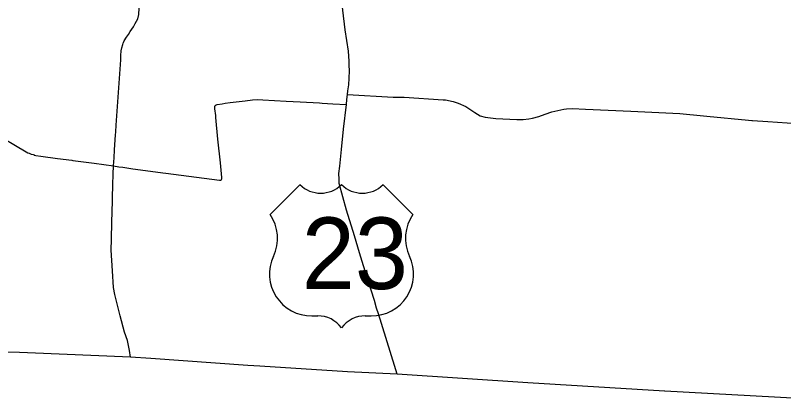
# Model space of a CAD drawing. Extents: x 0 to 34, y 0 to 22.
# Drawn here: x 5.072 to 6.458, y 14.434 to 15.124 of the extents above; entities that cross this region are included whole.
import ezdxf

# ---------------------------------------------------------------- set-up
doc = ezdxf.new("R2010")
doc.units = 0
for name, color, linetype in [('GM_X_County', 7, 'Continuous'), ('GM_X_State_Route', 7, 'Continuous'), ('GM_X_US_Route', 7, 'Continuous'), ('GM_X_US_Shield', 7, 'Continuous')]:
    doc.layers.add(name, color=color, linetype=linetype)

msp = doc.modelspace()

# ---------------------------------------------------------------- linework, layer by layer
at = {"layer": 'GM_X_County'}
msp.add_lwpolyline([(6.4853, 14.4341), (6.2434, 14.4473), (6.2427, 14.4474), (5.9966, 14.4624), (5.7606, 14.4783), (5.6711, 14.4822), (5.513, 14.4923), (5.4918, 14.4937), (5.3167, 14.5061), (5.2797, 14.5085), (5.0939, 14.5163), (5.08, 14.5169), (5.0551, 14.5178), (4.8851, 14.5227), (4.6999, 14.5295), (4.5093, 14.542), (4.3546, 14.5516), (4.3469, 14.5519), (4.1065, 14.5646)], dxfattribs=at)
at = {"layer": 'GM_X_State_Route'}
for points in [[(5.2669, 15.0743), (5.2673, 15.0755), (5.2687, 15.0786), (5.2726, 15.0851), (5.2761, 15.0899), (5.2796, 15.0952), (5.2855, 15.1033), (5.2886, 15.1093), (5.2929, 15.1182), (5.2948, 15.1255), (5.2956, 15.137), (5.2954, 15.1512), (5.2949, 15.1595)], [(5.2543, 14.9262), (5.2543, 14.9266), (5.2624, 15.0439), (5.2627, 15.0519), (5.2633, 15.0603), (5.2641, 15.0659), (5.2659, 15.0716), (5.2669, 15.0743)], [(5.6711, 14.982), (5.7537, 14.9772)], [(5.4336, 14.9438), (5.4322, 14.9561), (5.432, 14.96), (5.4328, 14.962), (5.4345, 14.9634), (5.4365, 14.964), (5.4455, 14.9652), (5.4509, 14.9659), (5.4599, 14.9672), (5.487, 14.9705), (5.4999, 14.9722), (5.5088, 14.9728), (5.5188, 14.9722)], [(5.5188, 14.9722), (5.5607, 14.9697), (5.5856, 14.9687), (5.621, 14.9666), (5.6256, 14.9664), (5.6451, 14.9652), (5.6692, 14.9635)], [(5.7537, 14.9772), (5.7562, 14.9771)], [(5.7562, 14.9771), (5.7668, 14.9772), (5.7732, 14.9768), (5.7733, 14.9768)], [(5.7733, 14.9768), (5.8438, 14.9721)], [(5.8438, 14.9721), (5.8438, 14.9721), (5.8477, 14.9719), (5.8616, 14.9694), (5.8708, 14.9664), (5.8845, 14.9599), (5.9011, 14.949), (5.9108, 14.9435), (5.9196, 14.9408), (5.9388, 14.9387), (5.9769, 14.9364), (5.988, 14.9366), (5.9985, 14.9381), (6.005, 14.9393), (6.0165, 14.9423), (6.0275, 14.9462), (6.04, 14.9506), (6.0453, 14.9519), (6.0503, 14.953), (6.0557, 14.954), (6.0612, 14.955), (6.0664, 14.9557), (6.077, 14.9563), (6.1006, 14.9553), (6.1825, 14.9515)], [(6.1825, 14.9515), (6.2707, 14.9474), (6.3135, 14.9431), (6.3191, 14.9426)], [(4.9733, 14.9467), (5.0253, 14.9173), (5.0305, 14.9147), (5.0915, 14.8785), (5.0945, 14.8768), (5.0974, 14.876), (5.1007, 14.8745), (5.1041, 14.8734), (5.1064, 14.8728), (5.1064, 14.8727)], [(5.3436, 14.8402), (5.4405, 14.8274), (5.4424, 14.8277), (5.4439, 14.8287), (5.4444, 14.8296), (5.4445, 14.8303), (5.4446, 14.832), (5.442, 14.8585), (5.4376, 14.9014), (5.434, 14.9404), (5.4336, 14.9438)], [(6.3191, 14.9426), (6.3945, 14.9353), (6.4007, 14.9349), (6.4018, 14.9349)], [(5.2535, 14.914), (5.2535, 14.9143), (5.2543, 14.9262)], [(6.4018, 14.9349), (6.4291, 14.9332), (6.4815, 14.9296), (6.4817, 14.9296)], [(5.2513, 14.8823), (5.2531, 14.9091)], [(5.2531, 14.9091), (5.2535, 14.914)], [(5.2503, 14.8677), (5.2513, 14.8823)], [(5.1064, 14.8727), (5.1091, 14.872), (5.1185, 14.8704), (5.1483, 14.8666), (5.1742, 14.8633)], [(5.2493, 14.8531), (5.2503, 14.8677)], [(5.1742, 14.8633), (5.1743, 14.8633), (5.1757, 14.8631), (5.2142, 14.8579), (5.2493, 14.8531)], [(5.2481, 14.819), (5.2486, 14.8382), (5.2493, 14.8531)], [(5.2493, 14.8531), (5.2589, 14.8517)], [(5.2589, 14.8517), (5.2662, 14.8507)], [(5.2662, 14.8507), (5.2843, 14.8481), (5.3339, 14.8415)], [(5.3339, 14.8415), (5.3382, 14.8409), (5.3436, 14.8402)], [(5.2473, 14.7898), (5.2474, 14.7956), (5.2481, 14.819)], [(5.2797, 14.5085), (5.278, 14.5204), (5.2745, 14.5386), (5.2693, 14.5537), (5.2615, 14.5831), (5.2515, 14.6213), (5.249, 14.6339), (5.2473, 14.6644), (5.2451, 14.7014), (5.2455, 14.7214), (5.2461, 14.7516), (5.2473, 14.7895), (5.2473, 14.7898)]]:
    msp.add_lwpolyline(points, dxfattribs=at)
at = {"layer": 'GM_X_US_Route'}
for points in [[(5.6735, 14.9989), (5.6736, 14.9995), (5.6744, 15.0107), (5.6748, 15.025), (5.6745, 15.0342), (5.6741, 15.0416), (5.673, 15.0597), (5.6673, 15.0983), (5.6628, 15.1338), (5.6567, 15.1857), (5.6515, 15.2308), (5.6393, 15.326), (5.6269, 15.4235), (5.6226, 15.4628), (5.6205, 15.4811), (5.6107, 15.5672), (5.6099, 15.575)], [(5.6711, 14.982), (5.672, 14.9883), (5.6735, 14.9989)], [(5.6692, 14.9635), (5.67, 14.973), (5.6711, 14.982)], [(5.6578, 14.8585), (5.6605, 14.8828), (5.6643, 14.9191), (5.6692, 14.9635)], [(5.6562, 14.8292), (5.6558, 14.8397), (5.6572, 14.8528), (5.6578, 14.8584), (5.6578, 14.8585)], [(5.6836, 14.7274), (5.6694, 14.7733), (5.6565, 14.8217), (5.6562, 14.8292)], [(5.7238, 14.597), (5.7197, 14.6106), (5.708, 14.6477), (5.693, 14.6966), (5.6836, 14.7274)], [(5.7606, 14.4783), (5.7559, 14.4934), (5.727, 14.5865), (5.7238, 14.597)]]:
    msp.add_lwpolyline(points, dxfattribs=at)
at = {"layer": 'GM_X_US_Shield'}
for p, q in [((5.5853, 14.8193), (5.5316, 14.7657)), ((5.7893, 14.7657), (5.7356, 14.8193)), ((5.6067, 14.5831), (5.6175, 14.5831)), ((5.7034, 14.5831), (5.7141, 14.5831))]:
    msp.add_line(p, q, dxfattribs=at)
for centre, radius, start, end in [((5.6229, 14.8577), 0.0537, 225.573, 314.427), ((5.698, 14.8577), 0.0537, 225.573, 314.427), ((5.47, 14.7225), 0.0752, 334.5471, 35.0009), ((5.8509, 14.7225), 0.0752, 144.9991, 205.4529), ((5.6059, 14.6583), 0.0752, 154.8319, 270.6383), ((5.715, 14.6583), 0.0752, 269.3617, 25.1681), ((5.6175, 14.5294), 0.0537, 36.8699, 90), ((5.7034, 14.5294), 0.0537, 90, 143.1301)]:
    msp.add_arc(centre, radius, start, end, dxfattribs=at)

# ---------------------------------------------------------------- texts
msp.add_text('23', height=0.12885, dxfattribs=at).set_placement((5.5887, 14.6314))

doc.saveas('drawing.dxf')
